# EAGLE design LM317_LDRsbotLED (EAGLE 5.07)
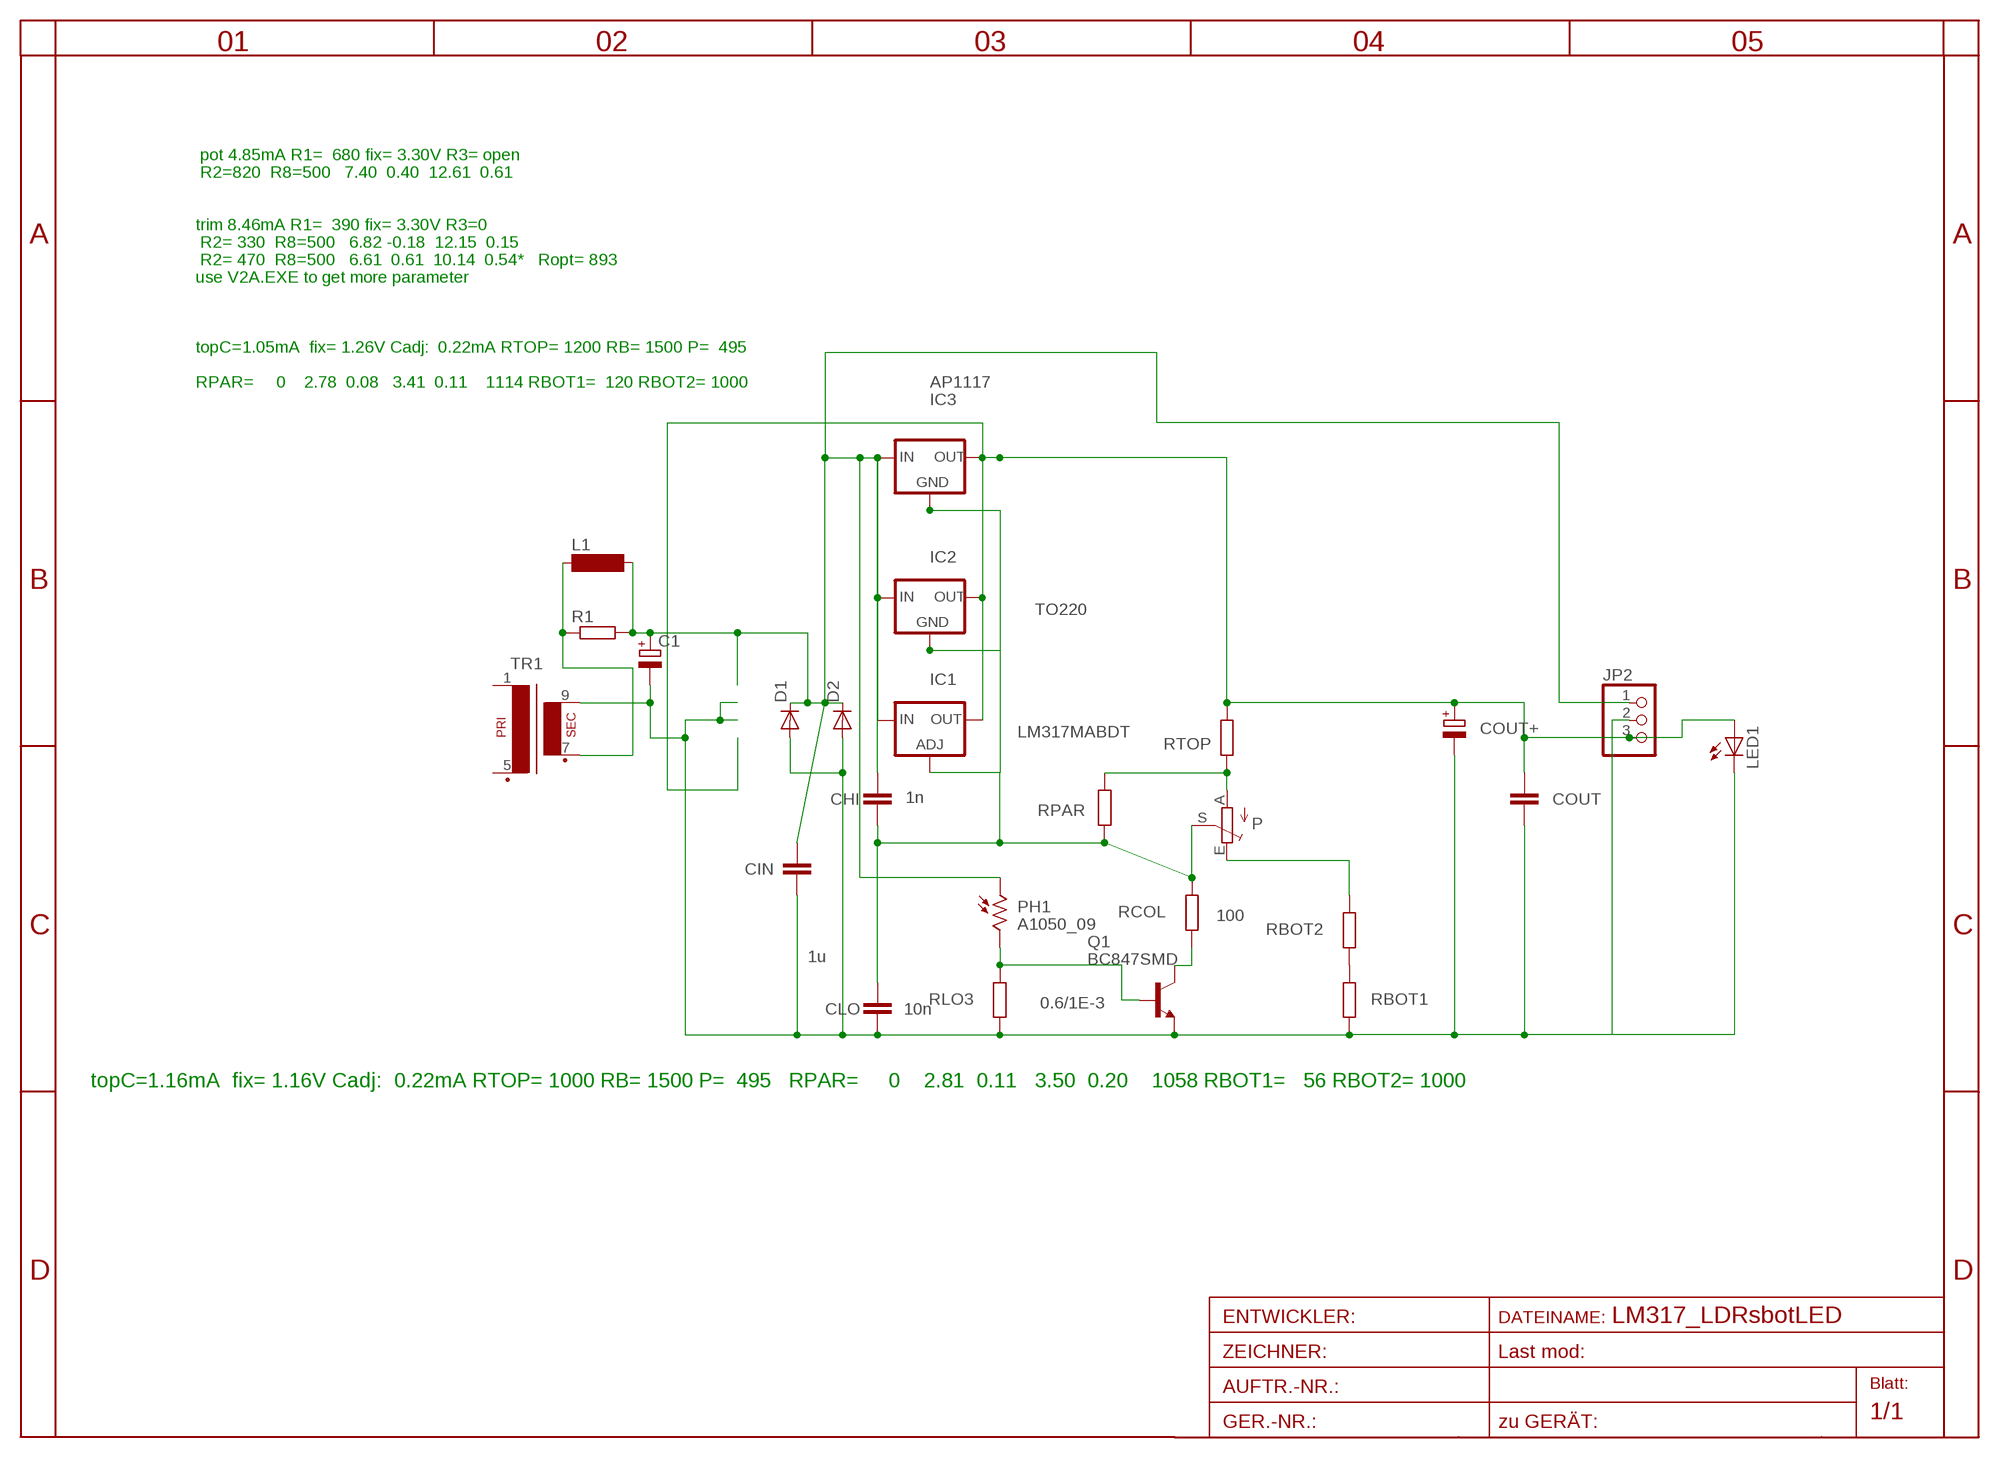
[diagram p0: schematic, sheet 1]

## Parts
C1  CPOL-EUE3.5-8  [E3,5-8]
CHI  1n  C-EUC0805  [C0805]
CIN  1u  C-EUC1206  [C1206]
CLO  10n  C-EUC0805  [C0805]
COUT  C-EUC1206  [C1206]
COUT+  CPOL-EUE2.5-6  [E2,5-6]
D1  DIODE-MINIMELF  [MINIMELF]
D2  DIODE-MINIMELF  [MINIMELF]
IC1  LM317MABDT  [DPACK]
IC2  TO220  78XXS  [78XXS]
IC3  AP1117  [SOT223]
JP2  PINHD-1X3  [1X03]
L1  BS11  [BS11]
LED1  LED1W_HOLE  [1W]
P  TRIM_EU-RAND160  [RANDL]
PH1  A1050_09  [T0-46-A10XX]
Q1  BC847SMD  [SOT23]
R1  R-EU_0204/2V  [0204V]
RBOT1  R-EU_R0805  [R0805]
RBOT2  R-EU_R0805  [R0805]
RCOL  100  R-EU_R0805  [R0805]
RLO3  0.6/1E-3  R-EU_R0805  [R0805]
RPAR  R-EU_R0805  [R0805]
RTOP  R-EU_R0805  [R0805]
TR1  VR11  [1WDRIVER]

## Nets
GND: C1.- CIN.2 CLO.2 COUT+.- COUT.2 D1.A D2.A JP2.2 LED1.C Q1.2(E) RBOT1.1 RLO3.1 TR1.9(S4)
IN: C1.+ CHI.1 CIN.1 D1.C D2.C IC1.3(IN) IC2.IN IC3.3(IN) JP2.1 L1.2 PH1.1 R1.2
N$1: P.E RBOT2.2
N$2: RBOT1.2 RBOT2.1
N$3: Q1.3(C) RCOL.1
N$4: CHI.2 CLO.1 IC1.1(ADJ) IC2.GND IC3.1(GND) P.S RCOL.2 RPAR.1
N$5: PH1.2 Q1.1(B) RLO3.2
N$7: P.A RPAR.2 RTOP.1
OUT: COUT+.+ COUT.1 IC1.4(OUT) IC2.OUT IC3.2(OUT) IC3.4(TAB) JP2.3 LED1.A RTOP.2
RED: L1.1 R1.1 TR1.7(S3)
Unconnected: TR1.1 TR1.5(P2)

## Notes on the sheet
- pot 4.85mA R1=  680 fix= 3.30V R3= open
- R2=820  R8=500   7.40  0.40  12.61  0.61
- trim 8.46mA R1=  390 fix= 3.30V R3=0
- R2= 330  R8=500   6.82 -0.18  12.15  0.15
- R2= 470  R8=500   6.61  0.61  10.14  0.54*   Ropt= 893
- use V2A.EXE to get more parameter
- topC=1.05mA  fix= 1.26V Cadj:  0.22mA RTOP= 1200 RB= 1500 P=  495
- RPAR=     0    2.78  0.08   3.41  0.11    1114 RBOT1=  120 RBOT2= 1000
- topC=1.16mA  fix= 1.16V Cadj:  0.22mA RTOP= 1000 RB= 1500 P=  495   RPAR=     0    2.81  0.11   3.50  0.20    1058 RBOT1=   56 RBOT2= 1000

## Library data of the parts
C1 COUT+ = rcl:CPOL-EU: POLARIZED CAPACITOR, European symbol
CHI CIN CLO COUT = rcl:C-EU: CAPACITOR, European symbol
D1 D2 = diode-1:DIODE-: DIODE
IC1 = v-reg:LM317?*: 500 mA Adjustable Output Positive Voltage Regulator Source: http://www.onsemi.co.jp .. LM317M-D.PDF
IC2 = v-reg:78XXS: VOLTAGE REGULATOR
IC3 = v-reg:AP1117
JP2 = pinhead:PINHD-1X3: PIN HEADER
L1 = inductor-neosid:BS: INDUCTOR
LED1 = led:LED: LED
P = pot:TRIM_EU-: POTENTIOMETER
PH1 = photo-elements:A10: Sensor Robust Light Sensing Applications
Q1 = transistor-npn:BC847*: NPN Transistor
R1 RBOT1 RBOT2 RCOL RLO3 RPAR RTOP = rcl:R-EU_: RESISTOR, European symbol
TR1 = trafo:VR11: TRANSFORMER 1 primary winding, 1 secondary winding BLOCK

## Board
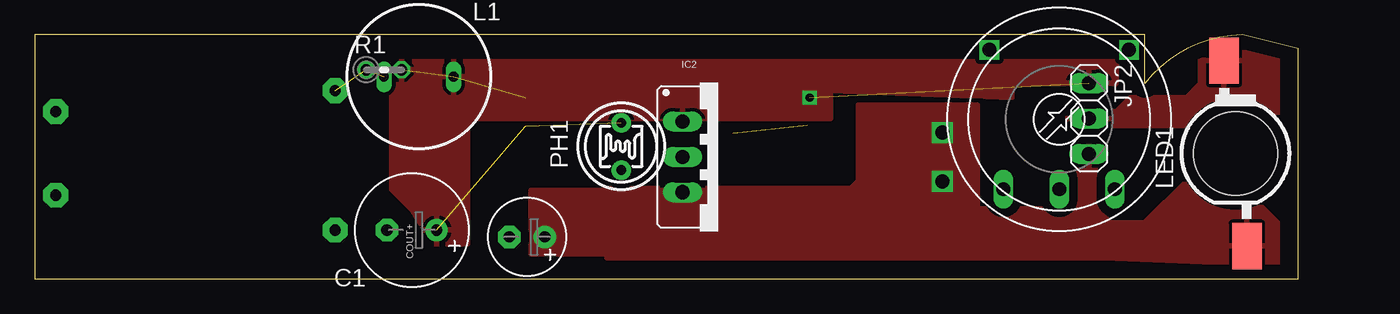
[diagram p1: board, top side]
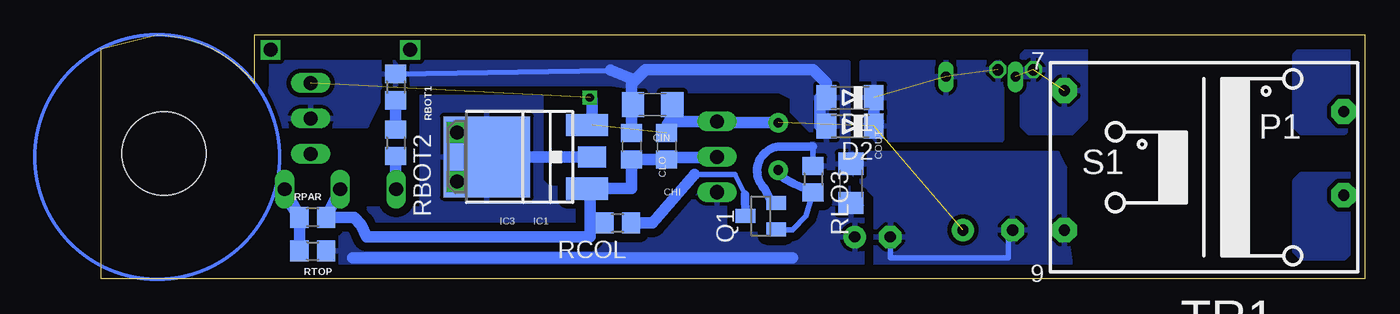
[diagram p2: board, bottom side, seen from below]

Size 90.5 x 17.5 mm. Coordinates in mm from the lower left corner, seen from the top.
Outline: 0,0 90.5,0 90.5,16.5 86.5,17.5 arc51 79.5,14 79.5,17.5 0,17.5 0,0
Copper layers (1*16): Top 0.035mm / dielectric 1.5mm / Bottom 0.035mm
Design rules "default *": minimum track width 10mil, minimum drill 20mil, track to track 8mil, track to pad 8mil, pad to pad 8mil, via to via 8mil, smd to smd 8mil, copper to edge 40mil, drill to drill 8mil, minimum pad ring 8mil, minimum via ring 8mil, stop-mask expansion 8mil, vias tented up to drill 0mil, thermal gap 10mil

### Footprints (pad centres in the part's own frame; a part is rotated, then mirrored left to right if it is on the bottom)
E3,5-8 = drill 0.813 pad 1.6 round: + -1.778,0 | drill 0.813 pad 1.6 octagon: - 1.778,0
C0805 = smd 1.3 x 1.5: 1 -0.95,0; 2 0.95,0
C1206 = smd 1.6 x 1.8: 1 -1.4,0; 2 1.4,0
E2,5-6 = drill 0.8 pad 1.6 round: + -1.27,0 | drill 0.8 pad 1.6 octagon: - 1.27,0
MINIMELF = smd 1.4 x 1.8: A 1.7,0; C -1.7,0
DPACK = smd 1.6 x 3: 1 -2.28,-4.8; 3 2.28,-4.8 | smd 5.8 x 6.2: 4 0,2.38
78XXS = drill 1.016 long: GND 0,-2.54; IN -2.54,-2.54; OUT 2.54,-2.54
SOT223 = smd 1.5 x 2: 1 -2.3,-3.15; 2 0,-3.15; 3 2.3,-3.15 | smd 3.8 x 2: 4 0,3.15
1X03 = drill 1.016 long: 1 -2.54,0; 2 0,0; 3 2.54,0
BS11 = drill 0.7 long: 1 -2.5,0; 2 2.5,0
1W = smd 3.3 x 2.1: A -6.65,-0.82; C 6.65,0.82 | hole 6: 0,0
RANDL = drill 1 long: A -4,5; E 4,5; S 0,5 | drill 1 square: P$1 -5,-5; P$2 5,-5
T0-46-A10XX = drill 0.7 pad 1.4 round: 1 -1.7,0; 2 1.7,0
SOT23 = smd 1 x 1.4: 1 -0.95,-1.1; 2 0.95,-1.1; 3 0,1.1
0204V = drill 0.813 octagon: 1 -1.27,0; 2 1.27,0
R0805 = smd 1.3 x 1.5: 1 -0.95,0; 2 0.95,0
1WDRIVER = drill 0.8 pad 1.778 octagon: 1 -10,2; 5 -10,-4; 7 10,-5.5; 9 10,4.5

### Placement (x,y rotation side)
C1  27,3.5 180 top
CHI  50,9.5 270 bottom
CIN  51,12.5 180 bottom
CLO  52.5,9.5 90 bottom
COUT  36.8,6.85 90 bottom
COUT+  35.25,3 180 top
D1  36.85,13 180 bottom
D2  36.85,10.95 180 bottom
IC1  60.5,8.75 90 bottom
IC2  48.93,8.75 270 top
IC3  58.5,8.75 90 bottom
JP2  75.5,11.5 270 top
L1  27.5,14.5 0 top
LED1  86,9 90 top
P  73.37,11.43 180 top
PH1  42,9.5 270 top
Q1  43.25,4.5 90 bottom
R1  25,15 0 top
RBOT1  69.4,13.75 270 bottom
RBOT2  69.4,9.75 270 bottom
RCOL  53.5,4 180 bottom
RLO3  39.5,7.15 270 bottom
RPAR  75.35,4.4 180 bottom
RTOP  75.35,2 0 bottom
TR1  11.5,8 180 bottom

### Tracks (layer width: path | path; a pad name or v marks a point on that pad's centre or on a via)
GND
  Bottom 0.406: RBOT1.1 54.06,14.92 54.01,14.97 | 42.45,5.45 Q1.2 | RLO3.1 39.5,9.5 | C1.- 25.5,3.5 25.5,1.5 33.98,1.5 COUT+.-
  Bottom 0.61: 42.45,5.45 43,6.5 arc127 42,9.5 39.5,9.5
  Bottom 0.813: 52.5,12.6 CLO.2 | D2.A 39,10.95 39,13 D1.A 38.55,14.05 39.5,15 51.5,15 52.25,14.25 | 52.25,14.25 52.5,14 52.5,12.6 | 52.5,12.6 CIN.2 | 52.25,14.25 54.01,14.97
  pour Bottom (isolate 0.305): 21.5,4 21.5,8 22,9 37,9 37,15.5 87.5,15.5 89.5,11 71.5,11 70.5,13 70.5,14 54,14 51.1,13.55 50,13.5 42,13.5 41,13 41,12 39.5,10.5 39.5,8 37,8 35,6 35,0.5 21,0.5
  pour Top: 74.5,12 74,12 74,11 89,11 89,13.5 89,17 83.5,17 83.5,15.5 83.5,14 82.5,13 78.5,13 77.5,12
IN  (via drill 0.6)  (6 unrouted)
  Bottom 0.406: IC1.3 55.35,11.03 IC3.3 | 49.31,11.29 49.7,11.5 | 46.3,11.2 IC2.IN
  Bottom 0.813: CIN.1 49.7,11.5 49.95,11.1 CHI.1 | 34.81,11.29 D2.C D1.C | IC3.3 55.35,12.85 v55.5,13 | IC2.IN 49.31,11.29 | PH1.1 46.3,11.2
  pour Top (isolate 0.305, rank 2): 25.54,15.56 77.5,15.56 77.5,15.5 77.44,14 70,14 70,13 57,13.5 57,11.5 31.5,11.5 31,11 31,2.5 28.54,2.5 27,5 25.54,6.46
  pour Bottom (isolate 0.305, rank 2): 26,10 26,15.5 36,15.5 36,11.5 35,10
N$1
  Bottom 0.813: RBOT2.2 69.4,6.46 P.E
N$2
  Bottom 0.813: RBOT2.1 RBOT1.2
N$3
  Bottom 0.406: 44.4,6.05 45.1,7.5 48,7.5
  Bottom 0.61: Q1.3 44.4,6.05
  Bottom 0.813: 48,7.5 51,4 RCOL.1
N$4
  Bottom 0.406: IC1.1 55.35,6.47 IC3.1 | IC2.GND 47.25,8.75 47.5,8.7 | 49.45,8.7 CHI.2 | 55.5,4 RCOL.2
  Bottom 0.813: CHI.2 CLO.1 52.5,6.5 52.53,6.47 IC1.1 | IC3.1 55.5,6.3 55.5,4 55.5,3 71.5,3 71.87,3.87 72.4,4.4 RPAR.1 73.4,6.4 P.S | 47.5,8.7 49.45,8.7
N$5
  Bottom 0.406: PH1.2 42,7.5 41.6,7.2 | RLO3.2 40,4.5 41,3.5 42.1,3.5 Q1.1
  Bottom 0.61: 41.6,7.2 40.9,6.85 RLO3.2
N$7
  Bottom 0.813: RPAR.2 77.34,6.4 P.A | RPAR.2 77.2,5.72 | RTOP.1 RPAR.2
N$8
  pour Bottom (isolate 0.305, rank 2): 0.5,16.5 4.5,16.5 5,16 5,11 4.5,10.5 1.5,10.5 0.5,11.5
  pour Bottom (isolate 0.305, rank 2): 0.5,7.5 4.5,7.5 5,7 5,2 4.5,1.5 1.5,1.5 0.5,2.5
OUT  (via drill 1)
  Bottom 0.406: IC1.4 65,8.75 v65,7
  Bottom 0.813: IC1.4 62.5,8.37 62.03,8.37 IC3.4 IC3.2 | 41,1.5 72.5,1.5
  other vias: 65,10.5
  pour Top (isolate 0.61, no thermals): 35.54,6.35 54.01,6.35 54.01,1.81 35.54,1.81
  pour Bottom (isolate 0.61, rank 2): 59,14 67.5,14 67.5,5 74,5 74,0.5 35.5,0.5 35.5,6.5 58.5,6.5 59,7
  pour Top (isolate 0.61): 59,12.45 67.5,12.45 67.5,5 74.5,5 74.5,9.5 76.5,9.5 76.5,4.5 77,4 79.5,4 82.5,7 86,7 89,4 89,1 76.5,1.5 41,1.5 41,6.5 58.5,6.5 59,7
RED  (2 unrouted)
  pour Bottom (isolate 0.305, rank 2): 20,16.5 24,16.5 24.5,16 24.5,11 24,10.5 21,10.5 20,11.5
(copper drawn outside any net)
  shapes: Bottom circle x1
